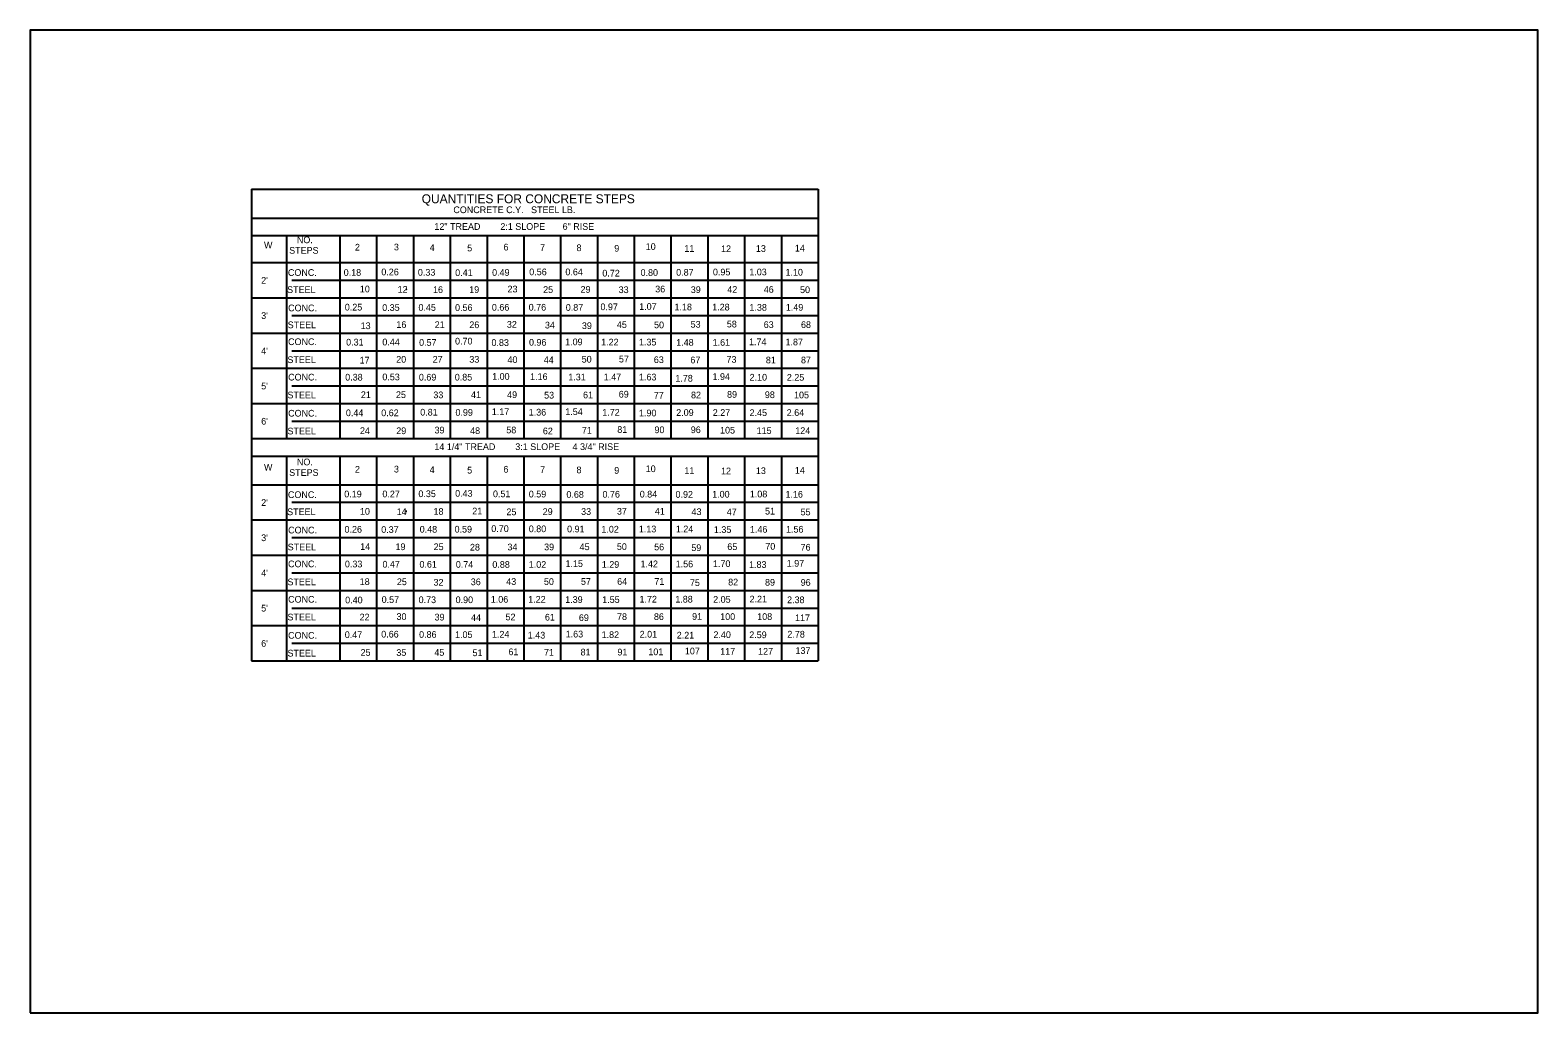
# Model space of a CAD drawing. Extents: x -439.5 to -408.2, y -792 to -771.6.
import ezdxf

# ---------------------------------------------------------------- set-up
doc = ezdxf.new("R2010")
doc.units = 0
doc.layers.add('Bridge-Named Boundary', color=7, linetype='Continuous')
doc.layers.add('Level 4', color=7, linetype='Continuous')

msp = doc.modelspace()

# ---------------------------------------------------------------- linework, layer by layer
at = {"layer": 'Bridge-Named Boundary'}
msp.add_lwpolyline([(-439.459, -791.984), (-408.209, -791.984), (-408.209, -771.609), (-439.459, -771.609)], close=True, dxfattribs=at)
at = {"layer": 'Level 4'}
for p, q in [((-434.87, -774.903), (-434.87, -784.686)), ((-434.87, -774.903), (-423.125, -774.903)), ((-423.125, -774.903), (-423.125, -784.686)), ((-434.87, -775.505), (-423.125, -775.505)), ((-434.87, -775.505), (-423.125, -775.505)), ((-434.87, -775.866), (-423.125, -775.866)), ((-434.143, -775.866), (-434.143, -780.079)), ((-433.04, -775.866), (-433.04, -780.079)), ((-432.278, -775.866), (-432.278, -780.079)), ((-431.515, -775.866), (-431.515, -780.079)), ((-430.753, -775.866), (-430.753, -780.079)), ((-429.989, -775.866), (-429.989, -780.079)), ((-429.227, -775.866), (-429.227, -780.079)), ((-428.464, -775.866), (-428.464, -780.079)), ((-427.702, -775.866), (-427.702, -780.079)), ((-426.938, -775.866), (-426.938, -780.079)), ((-426.176, -775.866), (-426.176, -780.079)), ((-425.412, -775.866), (-425.412, -780.079)), ((-424.65, -775.866), (-424.65, -780.079)), ((-423.887, -775.866), (-423.887, -780.079)), ((-434.87, -776.429), (-423.125, -776.429)), ((-434.038, -776.794), (-423.125, -776.794)), ((-434.87, -777.158), (-423.125, -777.158)), ((-434.038, -777.524), (-423.125, -777.524)), ((-434.87, -777.889), (-423.125, -777.889)), ((-434.038, -778.255), (-423.125, -778.255)), ((-434.87, -778.619), (-423.125, -778.619)), ((-434.038, -778.984), (-423.125, -778.984)), ((-434.87, -779.35), (-423.125, -779.35)), ((-434.038, -779.715), (-423.125, -779.715)), ((-434.87, -780.079), (-423.125, -780.079)), ((-434.87, -780.442), (-423.125, -780.442)), ((-434.143, -780.442), (-434.143, -784.686)), ((-433.04, -780.442), (-433.04, -784.686)), ((-432.278, -780.442), (-432.278, -784.686)), ((-431.515, -780.442), (-431.515, -784.686)), ((-430.753, -780.442), (-430.753, -784.686)), ((-429.989, -780.442), (-429.989, -784.686)), ((-429.227, -780.442), (-429.227, -784.686)), ((-428.464, -780.442), (-428.464, -784.686)), ((-427.702, -780.442), (-427.702, -784.686)), ((-426.938, -780.442), (-426.938, -784.686)), ((-426.176, -780.442), (-426.176, -784.686)), ((-425.412, -780.442), (-425.412, -784.686)), ((-424.65, -780.442), (-424.65, -784.686)), ((-423.887, -780.442), (-423.887, -784.686)), ((-434.87, -781.034), (-423.125, -781.034)), ((-434.038, -781.399), (-423.125, -781.399)), ((-434.87, -781.765), (-423.125, -781.765)), ((-434.038, -782.13), (-423.125, -782.13)), ((-434.87, -782.494), (-423.125, -782.494)), ((-434.038, -782.86), (-423.125, -782.86)), ((-434.87, -783.225), (-423.125, -783.225)), ((-434.038, -783.591), (-423.125, -783.591)), ((-434.87, -783.955), (-423.125, -783.955)), ((-434.038, -784.32), (-423.125, -784.32)), ((-434.87, -784.686), (-423.125, -784.686))]:
    msp.add_line(p, q, dxfattribs=at)
for centre in [(-431.616, -777.069), (-431.616, -781.674)]:
    msp.add_ellipse(centre, major_axis=(0.099, 0), ratio=0.96313, start_param=1.96543, end_param=2.160216, dxfattribs=at)

# ---------------------------------------------------------------- texts
for s, height, p in [('QUANTITIES FOR CONCRETE STEPS', 0.18523, (-431.343, -775.198)), ('CONCRETE C.Y.   STEEL LB.', 0.13893, (-430.687, -775.403)), ('12" TREAD        2:1 SLOPE       6" RISE', 0.13893, (-431.08, -775.75)), ('NO.', 0.1389, (-433.93, -776.026)), ('W', 0.139, (-434.612, -776.135)), ('STEPS', 0.1389, (-434.09, -776.245)), ('2', 0.139, (-432.727, -776.179)), ('3', 0.139, (-431.919, -776.175)), ('4', 0.139, (-431.178, -776.186)), ('5', 0.139, (-430.401, -776.196)), ('6', 0.139, (-429.649, -776.177)), ('7', 0.139, (-428.89, -776.187)), ('8', 0.139, (-428.135, -776.191)), ('9', 0.139, (-427.352, -776.201)), ('10', 0.1389, (-426.7, -776.167)), ('11', 0.1389, (-425.899, -776.206)), ('12', 0.1389, (-425.139, -776.212)), ('13', 0.1389, (-424.416, -776.206)), ('14', 0.1389, (-423.608, -776.199)), ('0.18', 0.1389, (-432.96, -776.703)), ('0.26', 0.1389, (-432.18, -776.692)), ('0.33', 0.1389, (-431.422, -776.7)), ('0.49', 0.1389, (-429.884, -776.703)), ('0.56', 0.1389, (-429.114, -776.691)), ('0.64', 0.1389, (-428.365, -776.691)), ('0.87', 0.1389, (-426.069, -776.7)), ('0.95', 0.1389, (-425.307, -776.694)), ('1.03', 0.1389, (-424.553, -776.692)), ('1.10', 0.1389, (-423.803, -776.698)), ("2'", 0.1389, (-434.67, -776.867)), ('CONC.', 0.1389, (-434.116, -776.704)), ('0.41', 0.1389, (-430.649, -776.706)), ('0.72', 0.1389, (-427.599, -776.717)), ('0.80', 0.1389, (-426.807, -776.704)), ('STEEL', 0.1389, (-434.132, -777.059)), ('10', 0.1389, (-432.626, -777.045)), ('12', 0.1389, (-431.842, -777.053)), ('16', 0.1389, (-431.109, -777.058)), ('19', 0.1389, (-430.358, -777.057)), ('23', 0.1389, (-429.564, -777.046)), ('25', 0.1389, (-428.826, -777.057)), ('29', 0.1389, (-428.051, -777.054)), ('33', 0.1389, (-427.261, -777.061)), ('36', 0.1389, (-426.503, -777.046)), ('39', 0.1389, (-425.766, -777.06)), ('42', 0.1389, (-425.009, -777.054)), ('46', 0.1389, (-424.254, -777.055)), ('50', 0.1389, (-423.501, -777.061)), ("3'", 0.1389, (-434.67, -777.597)), ('CONC.', 0.1389, (-434.112, -777.438)), ('0.25', 0.1389, (-432.937, -777.422)), ('0.35', 0.1389, (-432.162, -777.43)), ('0.45', 0.1389, (-431.411, -777.428)), ('0.56', 0.1389, (-430.652, -777.431)), ('0.66', 0.1389, (-429.889, -777.425)), ('0.76', 0.1389, (-429.126, -777.424)), ('0.87', 0.1389, (-428.357, -777.428)), ('0.97', 0.1389, (-427.638, -777.415)), ('1.07', 0.1389, (-426.835, -777.409)), ('1.18', 0.1389, (-426.104, -777.418)), ('1.28', 0.1389, (-425.322, -777.421)), ('1.38', 0.1389, (-424.55, -777.427)), ('1.49', 0.1389, (-423.796, -777.425)), ('STEEL', 0.1389, (-434.121, -777.789)), ('13', 0.1389, (-432.609, -777.808)), ('16', 0.1389, (-431.868, -777.782)), ('21', 0.1389, (-431.073, -777.785)), ('26', 0.1389, (-430.356, -777.788)), ('32', 0.1389, (-429.578, -777.779)), ('34', 0.1389, (-428.789, -777.794)), ('39', 0.1389, (-428.023, -777.806)), ('45', 0.1389, (-427.298, -777.784)), ('50', 0.1389, (-426.527, -777.79)), ('53', 0.1389, (-425.769, -777.778)), ('58', 0.1389, (-425.019, -777.773)), ('63', 0.1389, (-424.254, -777.785)), ('68', 0.1389, (-423.482, -777.784)), ('CONC.', 0.1389, (-434.113, -778.139)), ('0.31', 0.1389, (-432.909, -778.148)), ('0.44', 0.1389, (-432.159, -778.145)), ('0.57', 0.1389, (-431.397, -778.154)), ('0.70', 0.1389, (-430.652, -778.127)), ('0.83', 0.1389, (-429.897, -778.156)), ('0.96', 0.1389, (-429.119, -778.151)), ('1.09', 0.1389, (-428.37, -778.142)), ('1.22', 0.1389, (-427.624, -778.147)), ('1.35', 0.1389, (-426.84, -778.147)), ('1.48', 0.1389, (-426.068, -778.153)), ('1.61', 0.1389, (-425.313, -778.153)), ('1.74', 0.1389, (-424.559, -778.141)), ('1.87', 0.1389, (-423.803, -778.144)), ("4'", 0.1389, (-434.67, -778.328)), ('STEEL', 0.1389, (-434.126, -778.512)), ('17', 0.1389, (-432.63, -778.521)), ('20', 0.1389, (-431.871, -778.504)), ('27', 0.1389, (-431.116, -778.504)), ('33', 0.1389, (-430.356, -778.504)), ('40', 0.1389, (-429.566, -778.511)), ('44', 0.1389, (-428.814, -778.514)), ('50', 0.1389, (-428.027, -778.502)), ('57', 0.1389, (-427.256, -778.499)), ('63', 0.1389, (-426.532, -778.512)), ('67', 0.1389, (-425.774, -778.518)), ('73', 0.1389, (-425.026, -778.505)), ('81', 0.1389, (-424.21, -778.518)), ('87', 0.1389, (-423.482, -778.517)), ('CONC.', 0.1389, (-434.112, -778.873)), ('0.38', 0.1389, (-432.929, -778.874)), ('0.53', 0.1389, (-432.159, -778.869)), ('0.69', 0.1389, (-431.402, -778.874)), ('0.85', 0.1389, (-430.658, -778.874)), ('1.00', 0.1389, (-429.883, -778.858)), ('1.16', 0.1389, (-429.096, -778.862)), ('1.31', 0.1389, (-428.305, -778.871)), ('1.47', 0.1389, (-427.57, -778.87)), ('1.63', 0.1389, (-426.84, -778.872)), ('1.94', 0.1389, (-425.316, -778.861)), ('2.10', 0.1389, (-424.547, -778.875)), ('2.25', 0.1389, (-423.775, -778.877)), ("5'", 0.1389, (-434.67, -779.058)), ('1.78', 0.1389, (-426.086, -778.896)), ('STEEL', 0.1389, (-434.125, -779.243)), ('21', 0.1389, (-432.604, -779.237)), ('25', 0.1389, (-431.877, -779.237)), ('33', 0.1389, (-431.102, -779.241)), ('41', 0.1389, (-430.321, -779.237)), ('49', 0.1389, (-429.573, -779.237)), ('53', 0.1389, (-428.806, -779.247)), ('61', 0.1389, (-427.999, -779.243)), ('69', 0.1389, (-427.259, -779.227)), ('77', 0.1389, (-426.532, -779.25)), ('82', 0.1389, (-425.761, -779.243)), ('89', 0.1389, (-425.014, -779.232)), ('98', 0.1389, (-424.231, -779.238)), ('105', 0.1389, (-423.626, -779.243)), ("6'", 0.1389, (-434.67, -779.788)), ('CONC.', 0.1389, (-434.112, -779.621)), ('0.44', 0.1389, (-432.915, -779.613)), ('0.62', 0.1389, (-432.182, -779.613)), ('0.81', 0.1389, (-431.374, -779.6)), ('0.99', 0.1389, (-430.644, -779.605)), ('1.17', 0.1389, (-429.89, -779.589)), ('1.36', 0.1389, (-429.125, -779.6)), ('1.54', 0.1389, (-428.367, -779.589)), ('1.72', 0.1389, (-427.601, -779.603)), ('1.90', 0.1389, (-426.84, -779.616)), ('2.09', 0.1389, (-426.068, -779.607)), ('2.27', 0.1389, (-425.31, -779.607)), ('2.45', 0.1389, (-424.547, -779.61)), ('2.64', 0.1389, (-423.777, -779.608)), ('STEEL', 0.1389, (-434.125, -779.991)), ('24', 0.1389, (-432.623, -779.983)), ('29', 0.1389, (-431.871, -779.985)), ('39', 0.1389, (-431.077, -779.971)), ('48', 0.1389, (-430.339, -779.983)), ('58', 0.1389, (-429.59, -779.968)), ('62', 0.1389, (-428.832, -779.989)), ('71', 0.1389, (-428.022, -779.974)), ('81', 0.1389, (-427.289, -779.959)), ('90', 0.1389, (-426.518, -779.965)), ('96', 0.1389, (-425.766, -779.964)), ('105', 0.1389, (-425.159, -779.973)), ('115', 0.1389, (-424.401, -779.982)), ('124', 0.1389, (-423.6, -779.982)), ('14 1/4" TREAD        3:1 SLOPE     4 3/4" RISE', 0.13893, (-431.08, -780.315)), ('W', 0.139, (-434.612, -780.74)), ('NO.', 0.1389, (-433.93, -780.632)), ('STEPS', 0.1389, (-434.09, -780.851)), ('2', 0.139, (-432.727, -780.784)), ('3', 0.139, (-431.919, -780.78)), ('4', 0.139, (-431.178, -780.792)), ('5', 0.139, (-430.401, -780.802)), ('6', 0.139, (-429.649, -780.783)), ('7', 0.139, (-428.89, -780.793)), ('8', 0.139, (-428.135, -780.797)), ('9', 0.139, (-427.352, -780.807)), ('10', 0.1389, (-426.7, -780.773)), ('11', 0.1389, (-425.899, -780.812)), ('12', 0.1389, (-425.139, -780.818)), ('13', 0.1389, (-424.416, -780.812)), ('14', 0.1389, (-423.608, -780.804)), ('CONC.', 0.1389, (-434.116, -781.31)), ('0.19', 0.1389, (-432.948, -781.297)), ('0.27', 0.1389, (-432.158, -781.295)), ('0.35', 0.1389, (-431.412, -781.291)), ('0.43', 0.1389, (-430.65, -781.283)), ('0.51', 0.1389, (-429.866, -781.293)), ('0.59', 0.1389, (-429.124, -781.298)), ('0.68', 0.1389, (-428.344, -781.305)), ('0.76', 0.1389, (-427.596, -781.301)), ('0.84', 0.1389, (-426.824, -781.299)), ('0.92', 0.1389, (-426.082, -781.305)), ('1.00', 0.1389, (-425.323, -781.301)), ('1.08', 0.1389, (-424.542, -781.297)), ('1.16', 0.1389, (-423.803, -781.302)), ("2'", 0.1389, (-434.67, -781.473)), ('STEEL', 0.1389, (-434.132, -781.665)), ('10', 0.1389, (-432.623, -781.656)), ('14', 0.1389, (-431.862, -781.665)), ('18', 0.1389, (-431.098, -781.657)), ('21', 0.1389, (-430.295, -781.649)), ('25', 0.1389, (-429.588, -781.666)), ('29', 0.1389, (-428.835, -781.661)), ('33', 0.1389, (-428.039, -781.659)), ('37', 0.1389, (-427.297, -781.654)), ('41', 0.1389, (-426.51, -781.654)), ('43', 0.1389, (-425.75, -781.663)), ('47', 0.1389, (-425.02, -781.667)), ('51', 0.1389, (-424.227, -781.652)), ('55', 0.1389, (-423.49, -781.669)), ('0.70', 0.1389, (-429.901, -782.014)), ("3'", 0.1389, (-434.67, -782.203)), ('CONC.', 0.1389, (-434.112, -782.044)), ('0.26', 0.1389, (-432.943, -782.028)), ('0.37', 0.1389, (-432.182, -782.033)), ('0.48', 0.1389, (-431.385, -782.028)), ('0.59', 0.1389, (-430.662, -782.026)), ('0.80', 0.1389, (-429.124, -782.018)), ('0.91', 0.1389, (-428.33, -782.021)), ('1.02', 0.1389, (-427.619, -782.026)), ('1.13', 0.1389, (-426.843, -782.021)), ('1.24', 0.1389, (-426.076, -782.021)), ('1.35', 0.1389, (-425.287, -782.033)), ('1.46', 0.1389, (-424.54, -782.03)), ('1.56', 0.1389, (-423.792, -782.027)), ('STEEL', 0.1389, (-434.121, -782.395)), ('14', 0.1389, (-432.618, -782.385)), ('19', 0.1389, (-431.886, -782.39)), ('25', 0.1389, (-431.096, -782.39)), ('28', 0.1389, (-430.343, -782.399)), ('34', 0.1389, (-429.566, -782.395)), ('39', 0.1389, (-428.806, -782.393)), ('45', 0.1389, (-428.07, -782.39)), ('50', 0.1389, (-427.298, -782.386)), ('56', 0.1389, (-426.525, -782.394)), ('59', 0.1389, (-425.755, -782.409)), ('65', 0.1389, (-425.009, -782.389)), ('70', 0.1389, (-424.221, -782.381)), ('76', 0.1389, (-423.49, -782.4)), ("4'", 0.1389, (-434.67, -782.933)), ('CONC.', 0.1389, (-434.113, -782.745)), ('0.33', 0.1389, (-432.935, -782.748)), ('0.47', 0.1389, (-432.156, -782.752)), ('0.61', 0.1389, (-431.39, -782.753)), ('0.74', 0.1389, (-430.636, -782.757)), ('0.88', 0.1389, (-429.879, -782.757)), ('1.02', 0.1389, (-429.124, -782.757)), ('1.15', 0.1389, (-428.363, -782.739)), ('1.29', 0.1389, (-427.61, -782.757)), ('1.42', 0.1389, (-426.808, -782.745)), ('1.56', 0.1389, (-426.079, -782.747)), ('1.70', 0.1389, (-425.307, -782.741)), ('1.83', 0.1389, (-424.559, -782.759)), ('1.97', 0.1389, (-423.777, -782.733)), ('STEEL', 0.1389, (-434.126, -783.118)), ('18', 0.1389, (-432.628, -783.112)), ('25', 0.1389, (-431.858, -783.116)), ('32', 0.1389, (-431.098, -783.126)), ('36', 0.1389, (-430.326, -783.117)), ('43', 0.1389, (-429.591, -783.111)), ('50', 0.1389, (-428.81, -783.112)), ('57', 0.1389, (-428.043, -783.11)), ('64', 0.1389, (-427.292, -783.11)), ('71', 0.1389, (-426.522, -783.11)), ('75', 0.1389, (-425.784, -783.135)), ('82', 0.1389, (-424.991, -783.123)), ('89', 0.1389, (-424.227, -783.127)), ('96', 0.1389, (-423.488, -783.13)), ('CONC.', 0.1389, (-434.112, -783.479)), ('0.40', 0.1389, (-432.929, -783.494)), ('0.57', 0.1389, (-432.173, -783.485)), ('0.73', 0.1389, (-431.407, -783.489)), ('0.90', 0.1389, (-430.64, -783.489)), ('1.06', 0.1389, (-429.911, -783.48)), ('1.22', 0.1389, (-429.135, -783.479)), ('1.39', 0.1389, (-428.369, -783.484)), ('1.55', 0.1389, (-427.602, -783.486)), ('1.72', 0.1389, (-426.829, -783.477)), ('1.88', 0.1389, (-426.087, -783.477)), ('2.05', 0.1389, (-425.302, -783.481)), ('2.21', 0.1389, (-424.548, -783.475)), ('2.38', 0.1389, (-423.77, -783.49)), ("5'", 0.1389, (-434.67, -783.663)), ('STEEL', 0.1389, (-434.125, -783.848)), ('22', 0.1389, (-432.63, -783.847)), ('30', 0.1389, (-431.865, -783.837)), ('39', 0.1389, (-431.077, -783.849)), ('44', 0.1389, (-430.321, -783.858)), ('52', 0.1389, (-429.606, -783.845)), ('61', 0.1389, (-428.789, -783.85)), ('69', 0.1389, (-428.085, -783.86)), ('78', 0.1389, (-427.295, -783.838)), ('86', 0.1389, (-426.53, -783.839)), ('91', 0.1389, (-425.739, -783.835)), ('100', 0.1389, (-425.156, -783.837)), ('108', 0.1389, (-424.389, -783.837)), ('117', 0.1389, (-423.605, -783.863)), ('0.66', 0.1389, (-432.182, -784.202)), ('1.63', 0.1389, (-428.359, -784.201)), ('2.01', 0.1389, (-426.825, -784.203)), ('2.78', 0.1389, (-423.764, -784.203)), ("6'", 0.1389, (-434.67, -784.394)), ('CONC.', 0.1389, (-434.112, -784.227)), ('0.47', 0.1389, (-432.938, -784.213)), ('0.86', 0.1389, (-431.397, -784.209)), ('1.05', 0.1389, (-430.652, -784.211)), ('1.24', 0.1389, (-429.887, -784.204)), ('1.43', 0.1389, (-429.145, -784.223)), ('1.82', 0.1389, (-427.614, -784.213)), ('2.21', 0.1389, (-426.057, -784.223)), ('2.40', 0.1389, (-425.296, -784.213)), ('2.59', 0.1389, (-424.554, -784.215)), ('STEEL', 0.1389, (-434.125, -784.596)), ('25', 0.1389, (-432.61, -784.581)), ('35', 0.1389, (-431.869, -784.583)), ('45', 0.1389, (-431.081, -784.581)), ('51', 0.1389, (-430.29, -784.588)), ('61', 0.1389, (-429.546, -784.568)), ('71', 0.1389, (-428.809, -784.58)), ('81', 0.1389, (-428.05, -784.574)), ('91', 0.1389, (-427.286, -784.574)), ('101', 0.1389, (-426.646, -784.568)), ('107', 0.1389, (-425.888, -784.551)), ('117', 0.1389, (-425.156, -784.559)), ('127', 0.1389, (-424.371, -784.559)), ('137', 0.1389, (-423.596, -784.542))]:
    msp.add_text(s, height=height, dxfattribs=at).set_placement(p)

doc.saveas('drawing.dxf')
